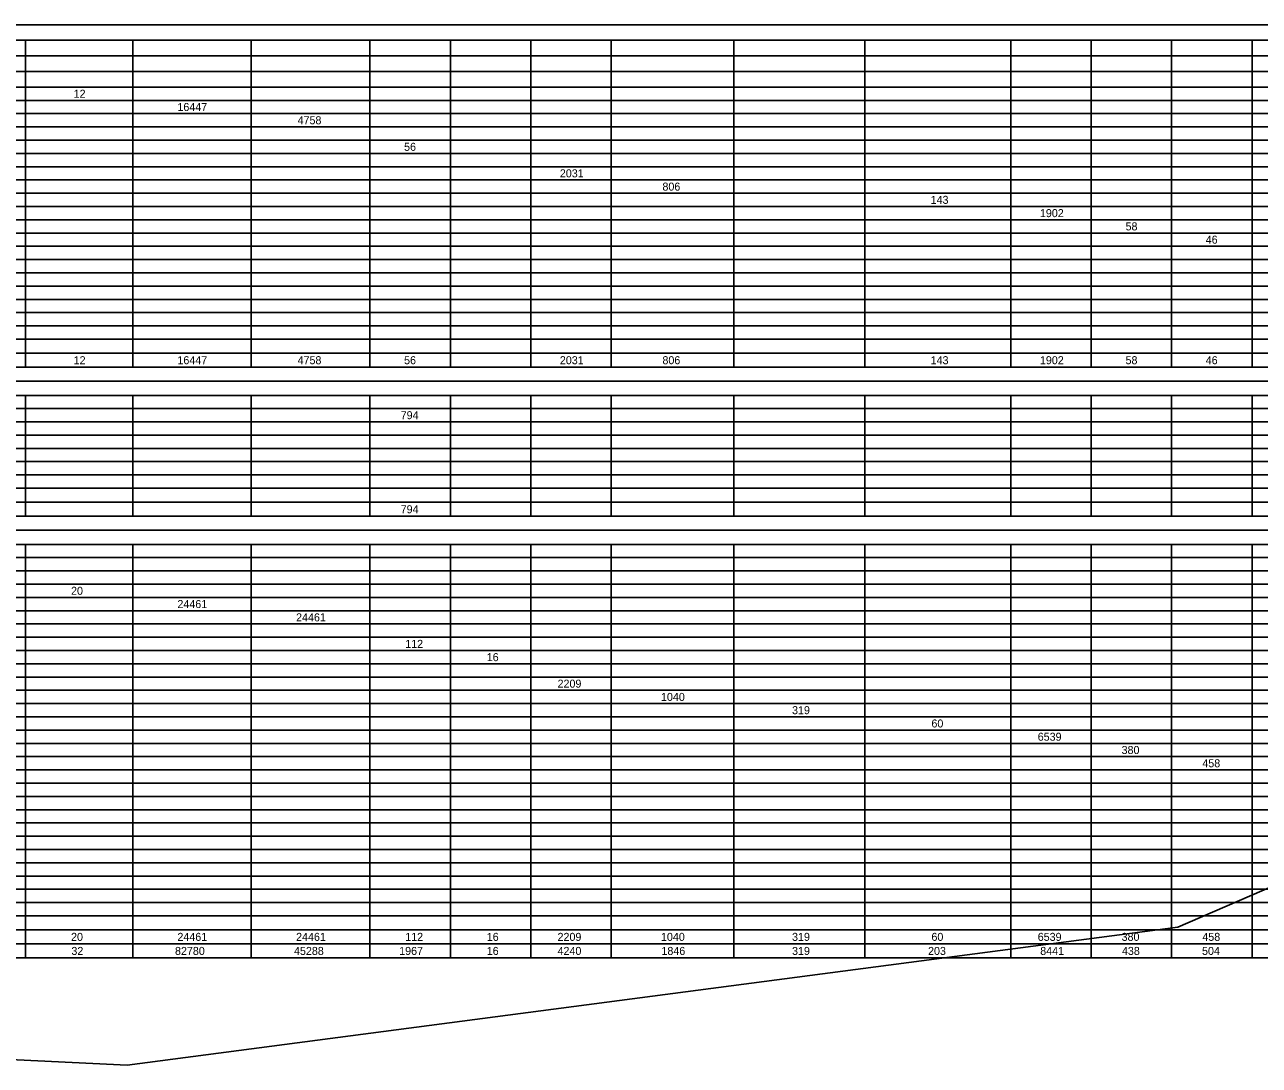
# Model space of a CAD drawing. Extents: x 1225909 to 1228704, y 151309 to 152305.
# Drawn here: x 1227205.7 to 1227705, y 151342 to 151763 of the extents above; entities that cross this region are included whole.
import ezdxf

# ---------------------------------------------------------------- set-up
doc = ezdxf.new("R2010")
doc.units = 0
doc.layers.add('R_Border', color=7, linetype='Continuous')
doc.layers.add('R_Dimension', color=7, linetype='Continuous')

msp = doc.modelspace()

# ---------------------------------------------------------------- linework, layer by layer
at = {"layer": 'R_Border'}
for points in [[(1228341.02, 151522.17), (1228050.15, 151561.5), (1227672.06, 151397.84)], [(1227672.06, 151397.84), (1227247.19, 151342), (1225968.58, 151404.15)]]:
    msp.add_lwpolyline(points, dxfattribs=at)
at = {"layer": 'R_Dimension'}
for p, q in [((1226577.42, 151763.01), (1228151.92, 151763.01)), ((1226577.42, 151756.69), (1228151.92, 151756.69)), ((1227205.96, 151624.42), (1227205.96, 151756.69)), ((1227249.36, 151624.42), (1227249.36, 151756.69)), ((1227297.35, 151624.42), (1227297.35, 151756.69)), ((1227345.33, 151624.42), (1227345.33, 151756.69)), ((1227377.85, 151624.42), (1227377.85, 151756.69)), ((1227410.36, 151624.42), (1227410.36, 151756.69)), ((1227442.88, 151624.42), (1227442.88, 151756.69)), ((1227492.44, 151624.42), (1227492.44, 151756.69)), ((1227545.48, 151624.42), (1227545.48, 151756.69)), ((1227604.51, 151624.42), (1227604.51, 151756.69)), ((1227637.03, 151624.42), (1227637.03, 151756.69)), ((1227669.54, 151624.42), (1227669.54, 151756.69)), ((1227702.06, 151624.42), (1227702.06, 151756.69)), ((1226577.42, 151750.38), (1228151.92, 151750.38)), ((1226577.42, 151744.07), (1228151.92, 151744.07)), ((1226577.42, 151737.75), (1228151.92, 151737.75)), ((1226577.42, 151732.39), (1228151.92, 151732.39)), ((1226577.42, 151727.02), (1228151.92, 151727.02)), ((1226577.42, 151721.65), (1228151.92, 151721.65)), ((1226577.42, 151716.29), (1228151.92, 151716.29)), ((1226577.42, 151710.92), (1228151.92, 151710.92)), ((1226577.42, 151705.55), (1228151.92, 151705.55)), ((1226577.42, 151700.18), (1228151.92, 151700.18)), ((1226577.42, 151694.82), (1228151.92, 151694.82)), ((1226577.42, 151689.45), (1228151.92, 151689.45)), ((1226577.42, 151684.08), (1228151.92, 151684.08)), ((1226577.42, 151678.72), (1228151.92, 151678.72)), ((1226577.42, 151673.35), (1228151.92, 151673.35)), ((1226577.42, 151667.98), (1228151.92, 151667.98)), ((1226577.42, 151662.62), (1228151.92, 151662.62)), ((1226577.42, 151657.25), (1228151.92, 151657.25)), ((1226577.42, 151651.88), (1228151.92, 151651.88)), ((1226577.42, 151646.52), (1228151.92, 151646.52)), ((1226577.42, 151641.15), (1228151.92, 151641.15)), ((1226577.42, 151635.78), (1228151.92, 151635.78)), ((1226577.42, 151630.1), (1228151.92, 151630.1)), ((1226577.42, 151624.42), (1228151.92, 151624.42)), ((1226577.42, 151618.74), (1228151.92, 151618.74)), ((1226577.42, 151613.05), (1228151.92, 151613.05)), ((1227205.96, 151564.12), (1227205.96, 151613.05)), ((1227249.36, 151564.12), (1227249.36, 151613.05)), ((1227297.35, 151564.12), (1227297.35, 151613.05)), ((1227345.33, 151564.12), (1227345.33, 151613.05)), ((1227377.85, 151564.12), (1227377.85, 151613.05)), ((1227410.36, 151564.12), (1227410.36, 151613.05)), ((1227442.88, 151564.12), (1227442.88, 151613.05)), ((1227492.44, 151564.12), (1227492.44, 151613.05)), ((1227545.48, 151564.12), (1227545.48, 151613.05)), ((1227604.51, 151564.12), (1227604.51, 151613.05)), ((1227637.03, 151564.12), (1227637.03, 151613.05)), ((1227669.54, 151564.12), (1227669.54, 151613.05)), ((1227702.06, 151564.12), (1227702.06, 151613.05)), ((1226577.42, 151607.69), (1228151.92, 151607.69)), ((1226577.42, 151602.32), (1228151.92, 151602.32)), ((1226577.42, 151596.95), (1228151.92, 151596.95)), ((1226577.42, 151591.59), (1228151.92, 151591.59)), ((1226577.42, 151586.22), (1228151.92, 151586.22)), ((1226577.42, 151580.85), (1228151.92, 151580.85)), ((1226577.42, 151575.49), (1228151.92, 151575.49)), ((1226577.42, 151569.81), (1228151.92, 151569.81)), ((1226577.42, 151564.12), (1228151.92, 151564.12)), ((1226577.42, 151558.44), (1228151.92, 151558.44)), ((1226577.42, 151552.76), (1228151.92, 151552.76)), ((1227205.96, 151385.44), (1227205.96, 151552.76)), ((1227249.36, 151385.44), (1227249.36, 151552.76)), ((1227297.35, 151385.44), (1227297.35, 151552.76)), ((1227345.33, 151385.44), (1227345.33, 151552.76)), ((1227377.85, 151385.44), (1227377.85, 151552.76)), ((1227410.36, 151385.44), (1227410.36, 151552.76)), ((1227442.88, 151385.44), (1227442.88, 151552.76)), ((1227492.44, 151385.44), (1227492.44, 151552.76)), ((1227545.48, 151385.44), (1227545.48, 151552.76)), ((1227604.51, 151385.44), (1227604.51, 151552.76)), ((1227637.03, 151385.44), (1227637.03, 151552.76)), ((1227669.54, 151385.44), (1227669.54, 151552.76)), ((1227702.06, 151385.44), (1227702.06, 151552.76)), ((1226577.42, 151547.39), (1228151.92, 151547.39)), ((1226577.42, 151542.02), (1228151.92, 151542.02)), ((1226577.42, 151536.66), (1228151.92, 151536.66)), ((1226577.42, 151531.29), (1228151.92, 151531.29)), ((1226577.42, 151525.92), (1228151.92, 151525.92)), ((1226577.42, 151520.56), (1228151.92, 151520.56)), ((1226577.42, 151515.19), (1228151.92, 151515.19)), ((1226577.42, 151509.82), (1228151.92, 151509.82)), ((1226577.42, 151504.46), (1228151.92, 151504.46)), ((1226577.42, 151499.09), (1228151.92, 151499.09)), ((1226577.42, 151493.72), (1228151.92, 151493.72)), ((1226577.42, 151488.36), (1228151.92, 151488.36)), ((1226577.42, 151482.99), (1228151.92, 151482.99)), ((1226577.42, 151477.62), (1228151.92, 151477.62)), ((1226577.42, 151472.26), (1228151.92, 151472.26)), ((1226577.42, 151466.89), (1228151.92, 151466.89)), ((1226577.42, 151461.52), (1228151.92, 151461.52)), ((1226577.42, 151456.16), (1228151.92, 151456.16)), ((1226577.42, 151450.79), (1228151.92, 151450.79)), ((1226577.42, 151445.42), (1228151.92, 151445.42)), ((1226577.42, 151440.06), (1228151.92, 151440.06)), ((1226577.42, 151434.69), (1228151.92, 151434.69)), ((1226577.42, 151429.32), (1228151.92, 151429.32)), ((1226577.42, 151423.96), (1228151.92, 151423.96)), ((1226577.42, 151418.59), (1228151.92, 151418.59)), ((1226577.42, 151413.22), (1228151.92, 151413.22)), ((1226577.42, 151407.86), (1228151.92, 151407.86)), ((1226577.42, 151402.49), (1228151.92, 151402.49)), ((1226577.42, 151396.81), (1228151.92, 151396.81)), ((1226577.42, 151391.13), (1228151.92, 151391.13)), ((1226577.42, 151385.44), (1228151.92, 151385.44))]:
    msp.add_line(p, q, dxfattribs=at)

# ---------------------------------------------------------------- texts
for s, p in [('12', (1227225.49, 151733.45)), ('16447', (1227267.46, 151728.08)), ('4758', (1227316.06, 151722.72)), ('56', (1227359.13, 151711.98)), ('2031', (1227422.13, 151701.25)), ('806', (1227463.62, 151695.88)), ('143', (1227572.09, 151690.52)), ('1902', (1227616.28, 151685.15)), ('58', (1227650.92, 151679.78)), ('46', (1227683.34, 151674.42)), ('12', (1227225.49, 151625.64)), ('16447', (1227267.46, 151625.64)), ('4758', (1227316.06, 151625.64)), ('56', (1227359.13, 151625.64)), ('2031', (1227422.13, 151625.64)), ('806', (1227463.62, 151625.64)), ('143', (1227572.09, 151625.64)), ('1902', (1227616.28, 151625.64)), ('58', (1227650.92, 151625.64)), ('46', (1227683.34, 151625.64)), ('794', (1227357.76, 151603.39)), ('794', (1227357.76, 151565.35)), ('20', (1227224.44, 151532.36)), ('24461', (1227267.46, 151526.99)), ('24461', (1227315.45, 151521.62)), ('112', (1227359.6, 151510.89)), ('16', (1227392.56, 151505.52)), ('2209', (1227421.2, 151494.79)), ('1040', (1227463.03, 151489.42)), ('319', (1227516.04, 151484.06)), ('60', (1227572.41, 151478.69)), ('6539', (1227615.4, 151473.32)), ('380', (1227649.32, 151467.95)), ('458', (1227681.98, 151462.59)), ('20', (1227224.44, 151392.35)), ('24461', (1227267.46, 151392.35)), ('24461', (1227315.45, 151392.35)), ('112', (1227359.6, 151392.35)), ('16', (1227392.56, 151392.35)), ('2209', (1227421.2, 151392.35)), ('1040', (1227463.03, 151392.35)), ('319', (1227516.04, 151392.35)), ('60', (1227572.41, 151392.35)), ('6539', (1227615.4, 151392.35)), ('380', (1227649.32, 151392.35)), ('458', (1227681.98, 151392.35)), ('32', (1227224.58, 151386.66)), ('82780', (1227266.48, 151386.66)), ('45288', (1227314.61, 151386.66)), ('1967', (1227357.15, 151386.66)), ('16', (1227392.56, 151386.66)), ('4240', (1227421.2, 151386.66)), ('1846', (1227463.21, 151386.66)), ('319', (1227516.04, 151386.66)), ('203', (1227571.04, 151386.66)), ('8441', (1227616.41, 151386.66)), ('438', (1227649.46, 151386.66)), ('504', (1227681.85, 151386.66))]:
    msp.add_text(s, height=3.238, dxfattribs=at).set_placement(p)

doc.saveas('drawing.dxf')
